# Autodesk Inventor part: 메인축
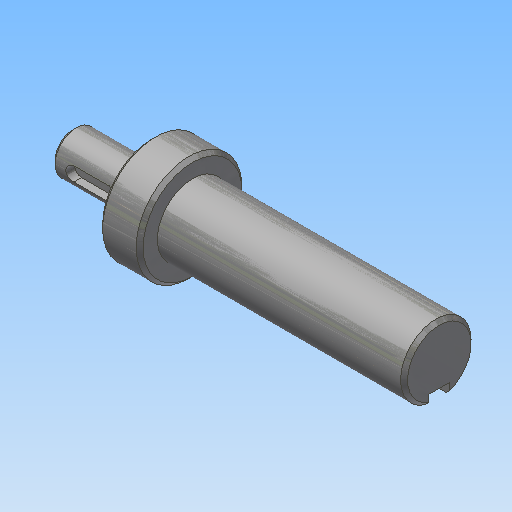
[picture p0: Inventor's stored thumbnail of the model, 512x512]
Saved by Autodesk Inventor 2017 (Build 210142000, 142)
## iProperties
Created: 2018-09
Part Number: 메인축
Document SubType Name: Modeling
Density: 7.86 g/cm^3
Material: 강철, 연강
Appearance: 강철
Mass: 251.954 g
Surface Area: 77.4403 cm^2
Volume: 32.0552 cm^3
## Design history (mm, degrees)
sketch "스케치1"
  geometry: L1 (34.997, -37.5)-(34.997, -77.5) reference; L2 (46.5, -38.401)-(46.5, -76.599) reference; L3 (12.497, -57.5)-(116.5, -57.5); L4 (12.497, -63.5)-(34.997, -63.5); L5 (34.997, -72.5)-(46.5, -72.5); L6 (46.5, -67.5)-(116.5, -67.5); L7 (116.5, -67.5)-(116.5, -57.5); L8 (12.497, -63.5)-(12.497, -57.5); 2 further points
  constraints: 12 end point, 5 point on line, 4 perpendicular, 1 midpoint, 1 parallel
  dimensions: "d0" = 20 diameter of L6 L3; "d1" = 30 diameter of L5 L3; "d2" = 22.5 distance of L4.start L4.end; "d3" = 70 distance of L6.start L6.end; "d5" = 12 diameter of L4 L3
revolve "회전1" sketch "스케치1" stored, may be unused: angle "d4" = 90 deg
chamfer "모따기1" distance "d6" = 1; stored, may be unused: second distance "d7" = 2, angle "d8" = 45 deg
node "작업 평면1"
sketch "스케치2"
  geometry: L1 (-11.25, -5)-(-11.25, 5) reference; L2 (-5.25, 2)-(4.75, 2); L3 (4.75, -2)-(-5.25, -2); A1 r 2 centre (4.75, 0) between (4.75, -2) and (4.75, 2); A2 r 2 centre (-5.25, 0) between (-5.25, 2) and (-5.25, -2); 2 further points
  constraints: 4 end point, 4 point on circle, 4 tangent, 2 centre point, 1 horizontal alignment, 1 midpoint, 1 parallel, 1 perpendicular
  dimensions: "d9" = 4 distance between parallel lines of L3 L2; "d10" = 14 dimension on A1 A2; "d11" = 4 distance edge to line of A2 L1
extrude "돌출1" cut sketch "스케치2" distance "d12" = 2.5; taper "d13" = 0 deg
node "작업 평면2"
sketch "스케치3"
  geometry: L1 (35, 9)-(35, -9) reference; L2 (35, 3)-(20, 3); L3 (20, -3)-(35, -3); A1 r 3 centre (20, 0) between (20, 3) and (20, -3); 2 further points
  constraints: 4 end point, 2 perpendicular, 2 point on circle, 2 point on line, 2 tangent, 1 centre point, 1 horizontal alignment, 1 midpoint
  dimensions: "d14" = 6 distance between parallel lines of L3 L2; "d15" = 18 dimension on A1 L1
extrude "돌출2" cut sketch "스케치3" distance "d16" = 3.5; taper "d17" = 0 deg
node "솔리드1"
node "참조1"
node "참조2"
